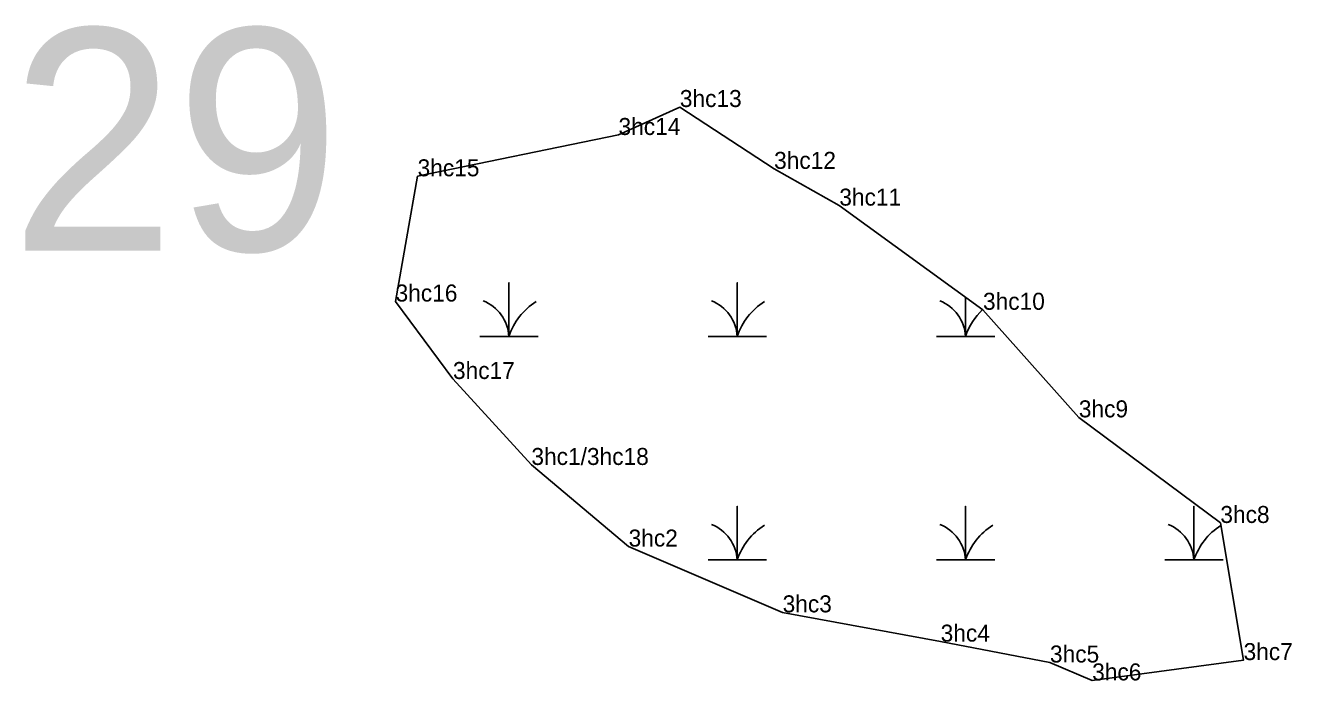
# Model space of a CAD drawing. Extents: x 2072529 to 2268796, y 436423 to 470406.
# Drawn here: x 2094811.4 to 2095184.3, y 459691.1 to 459883.9 of the extents above; entities that cross this region are included whole.
import ezdxf

# ---------------------------------------------------------------- set-up
doc = ezdxf.new("R2010")
doc.units = 0
for name, color, linetype in [('Default', 7, 'Continuous'), ('Exist Environmental Wetland Boundary Cogo Comment', 7, 'Continuous'), ('Exist Environmental Wetland Boundary Cogo Point CELL', 7, 'Continuous'), ('Old_Level_20', 7, 'Continuous')]:
    doc.layers.add(name, color=color, linetype=linetype)

msp = doc.modelspace()

# ---------------------------------------------------------------- linework, layer by layer
at = {"layer": 'Exist Environmental Wetland Boundary Cogo Point CELL'}
for points in [[(2094945.19, 459792.38), (2094953.79, 459792.38), (2094953.79, 459808.16), (2094953.79, 459792.38), (2094962.39, 459792.38)], [(2095012.44, 459792.38), (2095021.04, 459792.38), (2095021.04, 459808.16), (2095021.04, 459792.38), (2095029.64, 459792.38)], [(2095079.69, 459792.38), (2095088.29, 459792.38), (2095088.29, 459803.91)], [(2095088.29, 459803.91), (2095088.29, 459792.38), (2095096.89, 459792.38)], [(2095012.44, 459726.58), (2095021.04, 459726.58), (2095021.04, 459742.36), (2095021.04, 459726.58), (2095029.64, 459726.58)], [(2095079.69, 459726.58), (2095088.29, 459726.58), (2095088.29, 459742.36), (2095088.29, 459726.58), (2095096.89, 459726.58)], [(2095146.94, 459726.58), (2095155.54, 459726.58), (2095155.54, 459742.36), (2095155.54, 459726.58), (2095164.14, 459726.58)]]:
    msp.add_lwpolyline(points, dxfattribs=at)
for centre, radius, start, end in [((2094941.53, 459791.49), 12.3, 4.1403, 67.535), ((2094972.03, 459786.32), 19.22, 122.1274, 161.6222), ((2095008.78, 459791.49), 12.3, 4.1403, 67.535), ((2095039.28, 459786.32), 19.22, 122.1274, 161.6222), ((2095076.03, 459791.49), 12.3, 4.1403, 67.535), ((2095106.53, 459786.32), 19.22, 133.4504, 161.6222), ((2095008.78, 459725.69), 12.3, 4.1403, 67.535), ((2095039.28, 459720.52), 19.22, 122.1274, 161.6222), ((2095076.03, 459725.69), 12.3, 4.1403, 67.535), ((2095106.53, 459720.52), 19.22, 122.1274, 161.6222), ((2095143.28, 459725.69), 12.3, 4.1403, 67.535), ((2095173.78, 459720.52), 19.22, 122.5266, 161.6222)]:
    msp.add_arc(centre, radius, start, end, dxfattribs=at)
at = {"layer": 'Old_Level_20'}
for p, q in [((2095004.13, 459859.87), (2095004.13, 459859.87)), ((2094986.07, 459851.64), (2094986.07, 459851.64)), ((2095031.89, 459841.67), (2095031.89, 459841.67)), ((2094926.89, 459839.48), (2094926.89, 459839.48)), ((2095051.09, 459830.85), (2095051.09, 459830.85)), ((2094920.41, 459802.63), (2094920.41, 459802.63)), ((2095093.41, 459800.2), (2095093.41, 459800.2)), ((2094937.31, 459779.83), (2094937.31, 459779.83)), ((2095121.64, 459768.54), (2095121.64, 459768.54)), ((2094960.41, 459754.53), (2094960.41, 459754.53)), ((2095163.32, 459737.46), (2095163.32, 459737.46)), ((2094989.04, 459730.52), (2094989.04, 459730.52)), ((2095034.4, 459711.16), (2095034.4, 459711.16)), ((2095080.94, 459702.55), (2095080.94, 459702.55)), ((2095113.14, 459696.4), (2095113.14, 459696.4)), ((2095170.16, 459697.11), (2095170.16, 459697.11)), ((2095125.57, 459691.13), (2095125.57, 459691.13))]:
    msp.add_line(p, q, dxfattribs=at)
msp.add_lwpolyline([(2094926.89, 459839.48), (2094986.07, 459851.64), (2095004.13, 459859.87), (2095031.89, 459841.67), (2095051.09, 459830.85), (2095093.41, 459800.2), (2095121.64, 459768.54), (2095163.32, 459737.46), (2095170.16, 459697.11), (2095125.57, 459691.13), (2095113.14, 459696.4), (2095080.94, 459702.55), (2095034.4, 459711.16), (2094989.04, 459730.52), (2094960.41, 459754.53), (2094937.31, 459779.83), (2094920.41, 459802.63)], close=True, dxfattribs=at)

# ---------------------------------------------------------------- texts
at = {"layer": 'Default'}
msp.add_text('29', height=65.34, dxfattribs=at).set_placement((2094806.97, 459817.59))
at = {"layer": 'Exist Environmental Wetland Boundary Cogo Comment'}
for s, p in [('3hc13', (2095004.13, 459859.87)), ('3hc14', (2094986.07, 459851.64)), ('3hc12', (2095031.89, 459841.67)), ('3hc15', (2094926.89, 459839.48)), ('3hc11', (2095051.09, 459830.85)), ('3hc16', (2094920.41, 459802.63)), ('3hc10', (2095093.41, 459800.2)), ('3hc17', (2094937.31, 459779.83)), ('3hc9', (2095121.64, 459768.54)), ('3hc1/3hc18', (2094960.41, 459754.53)), ('3hc8', (2095163.32, 459737.46)), ('3hc2', (2094989.04, 459730.52)), ('3hc3', (2095034.4, 459711.16)), ('3hc4', (2095080.94, 459702.55)), ('3hc5', (2095113.14, 459696.4)), ('3hc7', (2095170.16, 459697.11)), ('3hc6', (2095125.57, 459691.13))]:
    msp.add_text(s, height=5, dxfattribs=at).set_placement(p)

doc.saveas('drawing.dxf')
